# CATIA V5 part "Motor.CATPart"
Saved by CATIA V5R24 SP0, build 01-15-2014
Part number: Motor
Bounding box of the stored display mesh (mm): x -10 to 20, y -25 to 35, z -10 to 10
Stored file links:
  C:\Users\Fatec\Desktop\Maquina componentes catia\Motor.CATPart
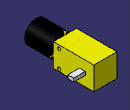
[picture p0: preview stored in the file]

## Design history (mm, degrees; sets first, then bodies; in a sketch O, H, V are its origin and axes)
Body1 (main body)
  Sketch1 on yz-plane, origin (0, 0, 0), H (0, 1, 0), V (0, 0, 1)
    point P1 (0, 10)
    line L1 (0, 10) -> (35, 10)
    line L2 (35, 10) -> (35, -10)
    line L3 (35, -10) -> (0, -10)
    line L4 (0, -10) -> (0, 10)
    distance L2 L4 = 35
    length L2 = 20
    coincidence: P1 V
    horizontal: L1 H, L3 H
    vertical: L2 V, L4 V
    symmetry: L1 L3 H
  Pad1: profile Sketch1, direction (1, 0, 0), length 10, mirrored extent
  Sketch2 on face of Pad1 from Sketch1.L4, origin (0, 0, 0), H (1, 0, 0), V (0, 0, 1)
  Sketch3 on zx-plane, origin (0, 0, 0), H (-1, 0, 0), V (0, 0, 1)
  Sketch4 on face of Pad1 from Sketch1.L4, origin (0, 0, 0), H (1, 0, 0), V (0, 0, 1)
    circle A1 centre (0, 0) radius 10
    radius A1 = 10
  Pad2: profile Sketch4, direction (0, -1, 0), length 25
  Sketch5 on end face of Pad1, origin (10, 0, 0), H (0, 1, 0), V (0, 0, 1)
    construction line L1 (25, 20) -> (25, -20)
    point P1 (25, 20)
    construction line L2 (-28.5004, 0) -> (47.4026, 0)
    point P3 (-28.5004, 0)
    reference projected point E1 (35, 10) from vertex [face of Pad1 from Sketch1.L1 | end face of Pad1 | face of Pad1 from Sketch1.L2]
    line L3 (22.5, 1.5) -> (27.5, 1.5)
    line L4 (27.5, 1.5) -> (27.5, -1.5)
    line L5 (27.5, -1.5) -> (22.5, -1.5)
    line L6 (22.5, -1.5) -> (22.5, 1.5)
    distance P1 E1 H = 10
    length L5 = 5
    distance L3 L5 = 3
    vertical: L1 V, L4 V, L6 V
    coincidence: P3 H
    horizontal: L2 H, L3 H, L5 H
    symmetry: L3 L5 H, L6 L4 L1
  Pad3: profile Sketch5, direction (1, 0, 0), length 10
  Sketch6 on end face of Pad1, origin (10, 0, 0), H (0, 1, 0), V (0, 0, 1)
    construction line L1 (5, 18.0748) -> (5, -19.1028)
    reference projected line E1 (35, -10) -> (35, 10) from edge [face of Pad1 from Sketch1.L2 | end face of Pad1]
    construction line L2 (-29.7327, 7) -> (44.9063, 7)
    construction line L3 (-34.2735, -8) -> (46.0415, -8)
    reference projected line E2 (35, 10) -> (0, 10) from edge [face of Pad1 from Sketch1.L1 | end face of Pad1]
    reference projected line E3 (35, 10) -> (0, 10) from edge [face of Pad1 from Sketch1.L1 | end face of Pad1]
    circle A1 centre (5, 7) radius 1.5
    point P7 (5, 7)
    circle A2 centre (5, -8) radius 1.5
    point P8 (5, -8)
    distance L1 E1 = 30
    distance L2 E2 = 3
    distance L3 E3 = 18
    radius A1 = 1.5
    radius A2 = 1.5
    vertical: L1 V
    horizontal: L2 H, L3 H
    coincidence: P7 L2, P7 L1, P8 L3, P8 L1
  Pocket1: profile Sketch6, direction (-1, 0, 0), through (limit type 6)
